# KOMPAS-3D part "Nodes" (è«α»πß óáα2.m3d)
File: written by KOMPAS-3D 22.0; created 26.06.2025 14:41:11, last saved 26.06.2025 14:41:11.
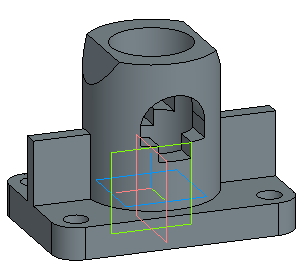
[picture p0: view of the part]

Document properties: Автор: Helen; Полное имя файла: D:\MY\WORK\MPEI\ППЭ_2025-2026\Варианты\Вар 2 СБ\Корпус вар2.m3d

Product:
- Part/product: Nodes

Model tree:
1. Операция без истории:1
